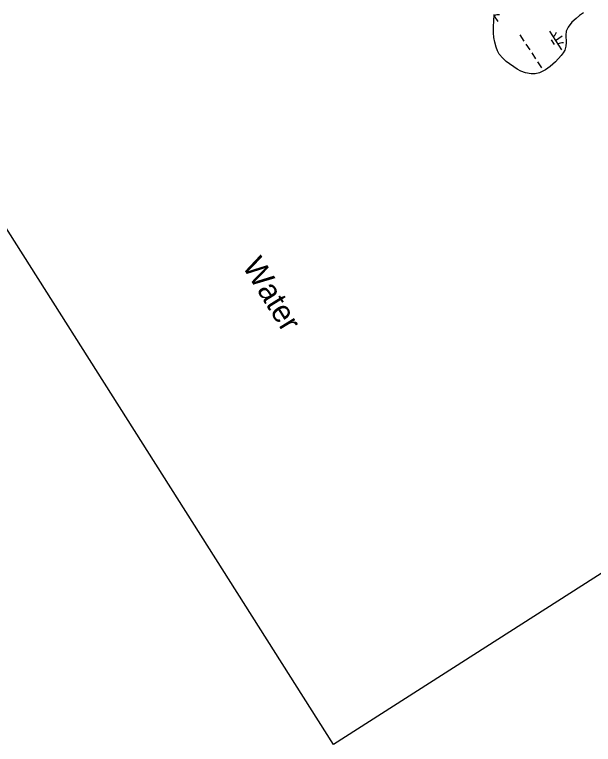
# Model space of a CAD drawing. Extents: x 3953924 to 3974542, y 193747 to 216192.
# Drawn here: x 3965342 to 3966639, y 196669 to 198304 of the extents above; entities that cross this region are included whole.
import ezdxf

# ---------------------------------------------------------------- set-up
doc = ezdxf.new("R2010")
doc.units = 0
for name, color, linetype in [('V-GRID-FRAM', 7, 'Continuous'), ('V-RIVR-IDEN', 7, 'Continuous'), ('V-WETL-SWMP', 7, 'Continuous')]:
    doc.layers.add(name, color=color, linetype=linetype)

msp = doc.modelspace()

# ---------------------------------------------------------------- linework, layer by layer
at = {"layer": 'V-GRID-FRAM'}
msp.add_lwpolyline([(3964669.3, 213787.9), (3972946, 201072.9), (3966057, 196668.5), (3957950.8, 209463.9), (3964669.3, 213787.9)], dxfattribs=at)
at = {"layer": 'V-WETL-SWMP'}
for p, q in [((3966415.9, 198289.4), (3966416.9, 198304.1)), ((3966416.6, 198300.3), (3966424.6, 198288)), ((3966600.1, 198295.2), (3966590.5, 198286.7)), ((3966607.4, 198301.5), (3966600.1, 198295.2)), ((3966616.6, 198308.1), (3966607.4, 198301.5)), ((3966415.2, 198276.9), (3966415.9, 198289.4)), ((3966415.4, 198262.6), (3966415.2, 198276.9)), ((3966590.5, 198286.7), (3966582, 198275.6)), ((3966415.9, 198252.8), (3966415.4, 198262.6)), ((3966540.3, 198267), (3966567.5, 198225.1)), ((3966578.1, 198266.6), (3966577.2, 198257.6)), ((3966582, 198275.6), (3966578.1, 198266.6)), ((3966418.4, 198242.2), (3966415.9, 198252.8)), ((3966474.4, 198258.1), (3966483.2, 198244.6)), ((3966544.2, 198246.9), (3966550.7, 198236.8)), ((3966553.9, 198246), (3966569, 198255.9)), ((3966577.2, 198257.6), (3966578, 198241.3)), ((3966421.2, 198231.2), (3966418.4, 198242.2)), ((3966424, 198222.4), (3966421.2, 198231.2)), ((3966487.5, 198237.9), (3966496.3, 198224.5)), ((3966577.4, 198233), (3966575, 198224.4)), ((3966578, 198241.3), (3966577.4, 198233)), ((3966428, 198215.2), (3966424, 198222.4)), ((3966435.8, 198206), (3966428, 198215.2)), ((3966500.6, 198217.8), (3966509.4, 198204.4)), ((3966566.8, 198212.5), (3966554.1, 198198)), ((3966571.1, 198218.4), (3966566.8, 198212.5)), ((3966575, 198224.4), (3966571.1, 198218.4)), ((3966443.6, 198199), (3966435.8, 198206)), ((3966467.7, 198181.6), (3966443.6, 198199)), ((3966513.7, 198197.7), (3966522.5, 198184.3)), ((3966554.1, 198198), (3966542.2, 198187.3)), ((3966476, 198176.9), (3966467.7, 198181.6)), ((3966531.5, 198180), (3966518.2, 198173.4)), ((3966542.2, 198187.3), (3966531.5, 198180)), ((3966486.5, 198173.3), (3966476, 198176.9)), ((3966499.6, 198170.8), (3966486.5, 198173.3)), ((3966508.3, 198171), (3966499.6, 198170.8)), ((3966518.2, 198173.4), (3966508.3, 198171))]:
    msp.add_line(p, q, dxfattribs=at)
for centre, start, end in [((3966426.3, 198286), 82.2901, 123.0277), ((3966539, 198269.3), 302.2901, 343.8338), ((3966569.2, 198223), 82.2901, 123.8337)]:
    msp.add_arc(centre, 17.6, start, end, dxfattribs=at)

# ---------------------------------------------------------------- texts
at = {"layer": 'V-RIVR-IDEN'}
msp.add_text('Water', height=50, rotation=301.6613, dxfattribs=at).set_placement((3965851.1, 197740.6))

doc.saveas('drawing.dxf')
